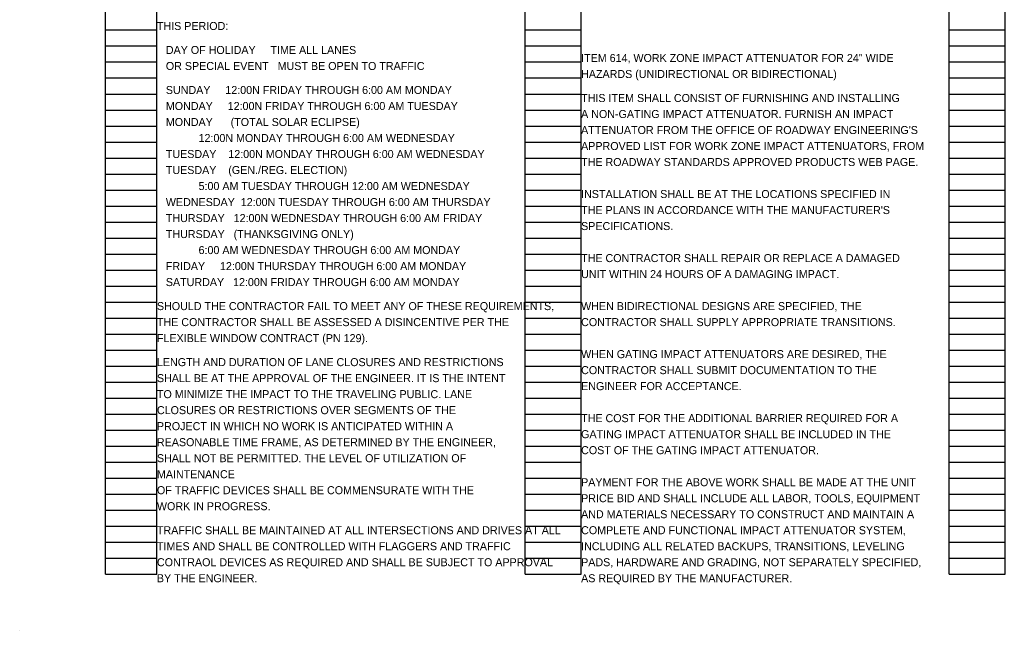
# Model space of a CAD drawing. Extents: x -21.1 to 72.2, y 0 to 46.6.
# Drawn here: x 38.43 to 55.67, y 0.23 to 10.91 of the extents above; entities that cross this region are included whole.
import ezdxf

# ---------------------------------------------------------------- set-up
doc = ezdxf.new("R2010")
doc.units = 0
doc.layers.add('SH_Data', color=7, linetype='Continuous')
doc.layers.add('SH_Text', color=7, linetype='Continuous')

msp = doc.modelspace()

# ---------------------------------------------------------------- linework, layer by layer
at = {"layer": 'SH_Data'}
for p, q in [((39.928, 1.206), (39.928, 21.366)), ((40.828, 1.206), (40.828, 21.366)), ((47.268, 1.206), (47.268, 21.366)), ((48.248, 1.206), (48.248, 21.366)), ((54.688, 1.206), (54.688, 21.366)), ((55.668, 1.206), (55.668, 21.366)), ((39.928, 10.726), (40.828, 10.726)), ((47.268, 10.726), (48.248, 10.726)), ((54.688, 10.726), (55.668, 10.726)), ((39.928, 10.446), (40.828, 10.446)), ((47.268, 10.446), (48.248, 10.446)), ((54.688, 10.446), (55.668, 10.446)), ((39.928, 10.166), (40.828, 10.166)), ((47.268, 10.166), (48.248, 10.166)), ((54.688, 10.166), (55.668, 10.166)), ((39.928, 9.886), (40.828, 9.886)), ((47.268, 9.886), (48.248, 9.886)), ((54.688, 9.886), (55.668, 9.886)), ((39.928, 9.606), (40.828, 9.606)), ((47.268, 9.606), (48.248, 9.606)), ((54.688, 9.606), (55.668, 9.606)), ((39.928, 9.326), (40.828, 9.326)), ((47.268, 9.326), (48.248, 9.326)), ((54.688, 9.326), (55.668, 9.326)), ((39.928, 9.046), (40.828, 9.046)), ((47.268, 9.046), (48.248, 9.046)), ((54.688, 9.046), (55.668, 9.046)), ((39.928, 8.766), (40.828, 8.766)), ((47.268, 8.766), (48.248, 8.766)), ((54.688, 8.766), (55.668, 8.766)), ((39.928, 8.486), (40.828, 8.486)), ((47.268, 8.486), (48.248, 8.486)), ((54.688, 8.486), (55.668, 8.486)), ((39.928, 8.206), (40.828, 8.206)), ((47.268, 8.206), (48.248, 8.206)), ((54.688, 8.206), (55.668, 8.206)), ((39.928, 7.926), (40.828, 7.926)), ((47.268, 7.926), (48.248, 7.926)), ((54.688, 7.926), (55.668, 7.926)), ((39.928, 7.646), (40.828, 7.646)), ((47.268, 7.646), (48.248, 7.646)), ((54.688, 7.646), (55.668, 7.646)), ((39.928, 7.366), (40.828, 7.366)), ((47.268, 7.366), (48.248, 7.366)), ((54.688, 7.366), (55.668, 7.366)), ((39.928, 7.086), (40.828, 7.086)), ((47.268, 7.086), (48.248, 7.086)), ((54.688, 7.086), (55.668, 7.086)), ((39.928, 6.806), (40.828, 6.806)), ((47.268, 6.806), (48.248, 6.806)), ((54.688, 6.806), (55.668, 6.806)), ((39.928, 6.526), (40.828, 6.526)), ((47.268, 6.526), (48.248, 6.526)), ((54.688, 6.526), (55.668, 6.526)), ((39.928, 6.246), (40.828, 6.246)), ((47.268, 6.246), (48.248, 6.246)), ((54.688, 6.246), (55.668, 6.246)), ((39.928, 5.966), (40.828, 5.966)), ((47.268, 5.966), (48.248, 5.966)), ((54.688, 5.966), (55.668, 5.966)), ((39.928, 5.686), (40.828, 5.686)), ((47.268, 5.686), (48.248, 5.686)), ((54.688, 5.686), (55.668, 5.686)), ((39.928, 5.406), (40.828, 5.406)), ((47.268, 5.406), (48.248, 5.406)), ((54.688, 5.406), (55.668, 5.406)), ((39.928, 5.126), (40.828, 5.126)), ((47.268, 5.126), (48.248, 5.126)), ((54.688, 5.126), (55.668, 5.126)), ((39.928, 4.846), (40.828, 4.846)), ((47.268, 4.846), (48.248, 4.846)), ((54.688, 4.846), (55.668, 4.846)), ((39.928, 4.566), (40.828, 4.566)), ((47.268, 4.566), (48.248, 4.566)), ((54.688, 4.566), (55.668, 4.566)), ((39.928, 4.286), (40.828, 4.286)), ((47.268, 4.286), (48.248, 4.286)), ((54.688, 4.286), (55.668, 4.286)), ((39.928, 4.006), (40.828, 4.006)), ((47.268, 4.006), (48.248, 4.006)), ((54.688, 4.006), (55.668, 4.006)), ((39.928, 3.726), (40.828, 3.726)), ((47.268, 3.726), (48.248, 3.726)), ((54.688, 3.726), (55.668, 3.726)), ((39.928, 3.446), (40.828, 3.446)), ((47.268, 3.446), (48.248, 3.446)), ((54.688, 3.446), (55.668, 3.446)), ((39.928, 3.166), (40.828, 3.166)), ((47.268, 3.166), (48.248, 3.166)), ((54.688, 3.166), (55.668, 3.166)), ((39.928, 2.886), (40.828, 2.886)), ((47.268, 2.886), (48.248, 2.886)), ((54.688, 2.886), (55.668, 2.886)), ((39.928, 2.606), (40.828, 2.606)), ((47.268, 2.606), (48.248, 2.606)), ((54.688, 2.606), (55.668, 2.606)), ((39.928, 2.326), (40.828, 2.326)), ((47.268, 2.326), (48.248, 2.326)), ((54.688, 2.326), (55.668, 2.326)), ((39.928, 2.046), (40.828, 2.046)), ((47.268, 2.046), (48.248, 2.046)), ((54.688, 2.046), (55.668, 2.046)), ((39.928, 1.766), (40.828, 1.766)), ((47.268, 1.766), (48.248, 1.766)), ((54.688, 1.766), (55.668, 1.766)), ((39.928, 1.486), (40.828, 1.486)), ((47.268, 1.486), (48.248, 1.486)), ((54.688, 1.486), (55.668, 1.486)), ((39.928, 1.206), (40.828, 1.206)), ((47.268, 1.206), (48.248, 1.206)), ((54.688, 1.206), (55.668, 1.206)), ((38.428, 0.226), (38.428, 0.226))]:
    msp.add_line(p, q, dxfattribs=at)

# ---------------------------------------------------------------- texts
at = {"layer": 'SH_Text'}
for s, p in [('THIS PERIOD:', (40.828, 10.726)), ('   DAY OF HOLIDAY     TIME ALL LANES', (40.828, 10.306)), ('ITEM 614, WORK ZONE IMPACT ATTENUATOR FOR 24" WIDE', (48.248, 10.166)), ('   OR SPECIAL EVENT   MUST BE OPEN TO TRAFFIC', (40.828, 10.026)), ('HAZARDS (UNIDIRECTIONAL OR BIDIRECTIONAL)', (48.248, 9.886)), ('   SUNDAY     12:00N FRIDAY THROUGH 6:00 AM MONDAY', (40.828, 9.606)), ('THIS ITEM SHALL CONSIST OF FURNISHING AND INSTALLING', (48.248, 9.466)), ('   MONDAY     12:00N FRIDAY THROUGH 6:00 AM TUESDAY', (40.828, 9.326)), ('A NON-GATING IMPACT ATTENUATOR. FURNISH AN IMPACT', (48.248, 9.186)), ('   MONDAY      (TOTAL SOLAR ECLIPSE)', (40.828, 9.046)), ("ATTENUATOR FROM THE OFFICE OF ROADWAY ENGINEERING'S", (48.248, 8.906)), ('              12:00N MONDAY THROUGH 6:00 AM WEDNESDAY', (40.828, 8.766)), ('   TUESDAY    12:00N MONDAY THROUGH 6:00 AM WEDNESDAY', (40.828, 8.486)), ('APPROVED LIST FOR WORK ZONE IMPACT ATTENUATORS, FROM', (48.248, 8.626)), ('THE ROADWAY STANDARDS APPROVED PRODUCTS WEB PAGE.', (48.248, 8.346)), ('   TUESDAY    (GEN./REG. ELECTION)', (40.828, 8.206)), ('              5:00 AM TUESDAY THROUGH 12:00 AM WEDNESDAY', (40.828, 7.926)), ('   WEDNESDAY  12:00N TUESDAY THROUGH 6:00 AM THURSDAY', (40.828, 7.646)), ('INSTALLATION SHALL BE AT THE LOCATIONS SPECIFIED IN', (48.248, 7.786)), ("THE PLANS IN ACCORDANCE WITH THE MANUFACTURER'S", (48.248, 7.506)), ('   THURSDAY   12:00N WEDNESDAY THROUGH 6:00 AM FRIDAY', (40.828, 7.366)), ('SPECIFICATIONS.', (48.248, 7.226)), ('   THURSDAY   (THANKSGIVING ONLY)', (40.828, 7.086)), ('              6:00 AM WEDNESDAY THROUGH 6:00 AM MONDAY', (40.828, 6.806)), ('THE CONTRACTOR SHALL REPAIR OR REPLACE A DAMAGED', (48.248, 6.666)), ('   FRIDAY     12:00N THURSDAY THROUGH 6:00 AM MONDAY', (40.828, 6.526)), ('   SATURDAY   12:00N FRIDAY THROUGH 6:00 AM MONDAY', (40.828, 6.246)), ('UNIT WITHIN 24 HOURS OF A DAMAGING IMPACT.', (48.248, 6.386)), ('SHOULD THE CONTRACTOR FAIL TO MEET ANY OF THESE REQUIREMENTS,', (40.828, 5.826)), ('WHEN BIDIRECTIONAL DESIGNS ARE SPECIFIED, THE', (48.248, 5.826)), ('THE CONTRACTOR SHALL BE ASSESSED A DISINCENTIVE PER THE', (40.828, 5.546)), ('CONTRACTOR SHALL SUPPLY APPROPRIATE TRANSITIONS.', (48.248, 5.546)), ('FLEXIBLE WINDOW CONTRACT (PN 129).', (40.828, 5.266)), ('WHEN GATING IMPACT ATTENUATORS ARE DESIRED, THE', (48.248, 4.986)), ('LENGTH AND DURATION OF LANE CLOSURES AND RESTRICTIONS ', (40.828, 4.846)), ('CONTRACTOR SHALL SUBMIT DOCUMENTATION TO THE', (48.248, 4.706)), ('SHALL BE AT THE APPROVAL OF THE ENGINEER. IT IS THE INTENT ', (40.828, 4.566)), ('ENGINEER FOR ACCEPTANCE.', (48.248, 4.426)), ('TO MINIMIZE THE IMPACT TO THE TRAVELING PUBLIC. LANE ', (40.828, 4.286)), ('CLOSURES OR RESTRICTIONS OVER SEGMENTS OF THE ', (40.828, 4.006)), ('THE COST FOR THE ADDITIONAL BARRIER REQUIRED FOR A', (48.248, 3.866)), ('PROJECT IN WHICH NO WORK IS ANTICIPATED WITHIN A ', (40.828, 3.726)), ('GATING IMPACT ATTENUATOR SHALL BE INCLUDED IN THE', (48.248, 3.586)), ('REASONABLE TIME FRAME, AS DETERMINED BY THE ENGINEER, ', (40.828, 3.446)), ('SHALL NOT BE PERMITTED. THE LEVEL OF UTILIZATION OF ', (40.828, 3.166)), ('COST OF THE GATING IMPACT ATTENUATOR.', (48.248, 3.306)), ('MAINTENANCE', (40.828, 2.886)), ('PAYMENT FOR THE ABOVE WORK SHALL BE MADE AT THE UNIT', (48.248, 2.746)), ('OF TRAFFIC DEVICES SHALL BE COMMENSURATE WITH THE ', (40.828, 2.606)), ('PRICE BID AND SHALL INCLUDE ALL LABOR, TOOLS, EQUIPMENT', (48.248, 2.466)), ('WORK IN PROGRESS.', (40.828, 2.326)), ('AND MATERIALS NECESSARY TO CONSTRUCT AND MAINTAIN A', (48.248, 2.186)), ('TRAFFIC SHALL BE MAINTAINED AT ALL INTERSECTIONS AND DRIVES AT ALL ', (40.828, 1.906)), ('COMPLETE AND FUNCTIONAL IMPACT ATTENUATOR SYSTEM,', (48.248, 1.906)), ('TIMES AND SHALL BE CONTROLLED WITH FLAGGERS AND TRAFFIC ', (40.828, 1.626)), ('INCLUDING ALL RELATED BACKUPS, TRANSITIONS, LEVELING', (48.248, 1.626)), ('CONTRAOL DEVICES AS REQUIRED AND SHALL BE SUBJECT TO APPROVAL ', (40.828, 1.346)), ('PADS, HARDWARE AND GRADING, NOT SEPARATELY SPECIFIED,', (48.248, 1.346)), ('BY THE ENGINEER.', (40.828, 1.066)), ('AS REQUIRED BY THE MANUFACTURER.', (48.248, 1.066))]:
    msp.add_text(s, height=0.14, dxfattribs=at).set_placement(p)

doc.saveas('drawing.dxf')
